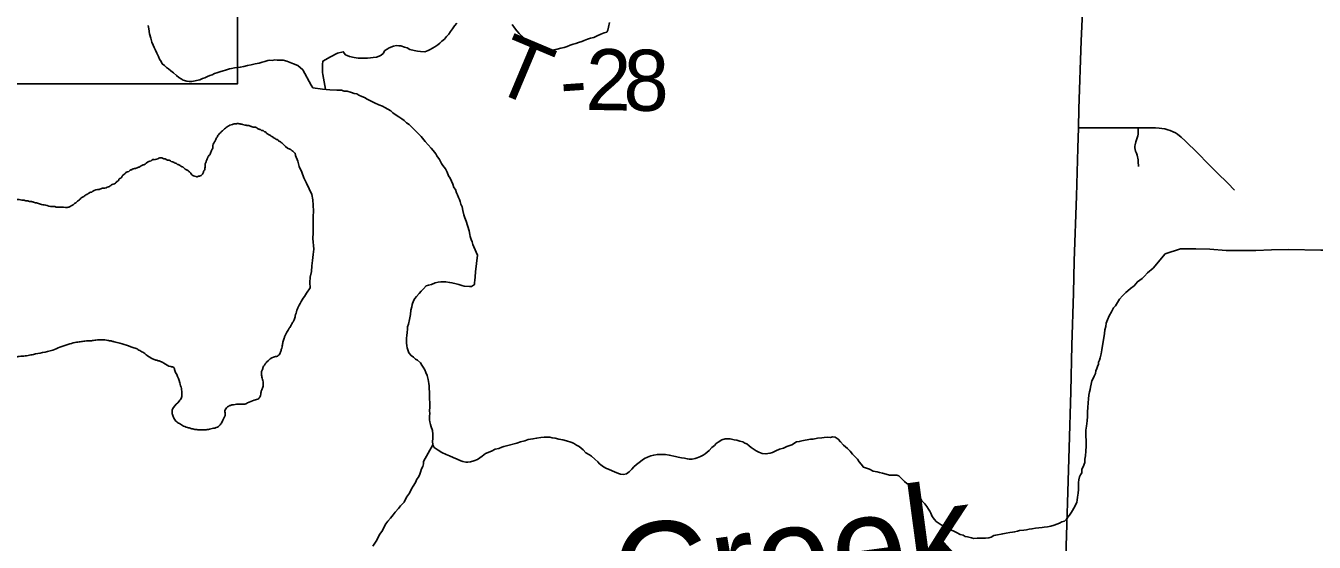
# Model space of a CAD drawing. Extents: x 0 to 34, y 0 to 22.
# Drawn here: x 26.822 to 28.021, y 15.894 to 16.375 of the extents above; entities that cross this region are included whole.
import ezdxf

# ---------------------------------------------------------------- set-up
doc = ezdxf.new("R2010")
doc.units = 0
for name, color, linetype in [('GM_X_City_Street', 7, 'Continuous'), ('GM_X_Minor_Lake', 7, 'Continuous'), ('GM_X_Minor_River', 7, 'Continuous'), ('GM_X_Minor_River_Text', 7, 'Continuous'), ('GM_X_State_Route', 7, 'Continuous'), ('GM_X_Township_Road_Text', 7, 'Continuous'), ('SH_Masking', 7, 'Continuous'), ('SH_Text', 7, 'Continuous')]:
    doc.layers.add(name, color=color, linetype=linetype)

msp = doc.modelspace()

# ---------------------------------------------------------------- linework, layer by layer
at = {"layer": 'GM_X_City_Street'}
for points in [[(27.8013, 16.2796), (27.8121, 16.2796), (27.8175, 16.2796), (27.8364, 16.2796), (27.857, 16.2797), (27.8646, 16.2797), (27.873, 16.2796), (27.8763, 16.2794), (27.8788, 16.2791), (27.8817, 16.2786), (27.8844, 16.2779), (27.8868, 16.2771), (27.8895, 16.276), (27.8916, 16.2749), (27.8934, 16.2737), (27.8969, 16.2711), (27.9007, 16.2675), (27.9123, 16.256), (27.9221, 16.2462), (27.9305, 16.2377), (27.9402, 16.2281), (27.9465, 16.2218)], [(27.8572, 16.2437), (27.857, 16.2485), (27.8569, 16.2498), (27.8567, 16.2516), (27.8564, 16.2528), (27.8559, 16.2543), (27.8552, 16.2561), (27.8544, 16.2579), (27.854, 16.2594), (27.8537, 16.261), (27.8537, 16.2626), (27.854, 16.264), (27.8547, 16.2665), (27.8561, 16.2705), (27.8566, 16.2723), (27.8568, 16.2738), (27.857, 16.2769), (27.857, 16.2797)]]:
    msp.add_lwpolyline(points, dxfattribs=at)
at = {"layer": 'GM_X_Minor_Lake'}
msp.add_lwpolyline([(27.0831, 16.126), (27.0863, 16.1308), (27.086, 16.1358), (27.0863, 16.1409), (27.0877, 16.1459), (27.088, 16.1513), (27.0887, 16.1563), (27.0893, 16.1617), (27.0897, 16.1667), (27.089, 16.1768), (27.0893, 16.1819), (27.0893, 16.1973), (27.0896, 16.2023), (27.0893, 16.2077), (27.089, 16.2127), (27.0879, 16.2178), (27.0856, 16.2228), (27.0829, 16.2282), (27.0806, 16.2332), (27.0785, 16.2383), (27.0762, 16.2436), (27.0748, 16.2487), (27.0728, 16.254), (27.0723, 16.256)], dxfattribs=at)
for points in [[(27.0723, 16.256), (27.0718, 16.2563), (27.0707, 16.2575), (27.0696, 16.2583), (27.0685, 16.2594), (27.0674, 16.2598), (27.0599, 16.2657), (27.0588, 16.2665), (27.0573, 16.2673), (27.0562, 16.2685), (27.0551, 16.2689), (27.0539, 16.2697), (27.0524, 16.2705), (27.0502, 16.272), (27.0487, 16.2728), (27.0476, 16.2736), (27.0461, 16.2744), (27.045, 16.2756), (27.0439, 16.276), (27.0427, 16.2771), (27.0412, 16.2772), (27.0401, 16.278), (27.039, 16.2784), (27.0379, 16.2788), (27.0367, 16.2796), (27.0345, 16.2804), (27.0333, 16.2804), (27.0318, 16.2808), (27.0307, 16.2812), (27.0292, 16.2817), (27.0281, 16.2817), (27.0269, 16.2821), (27.0258, 16.2821), (27.0235, 16.2829), (27.0224, 16.283), (27.0213, 16.2834), (27.0201, 16.2834), (27.019, 16.2838), (27.0179, 16.2835), (27.0156, 16.2835), (27.014, 16.2828), (27.0117, 16.2821), (27.0083, 16.2799), (27.0067, 16.2788), (27.004, 16.2762), (27.0028, 16.2751), (27.0017, 16.274), (27.0005, 16.2725), (26.9997, 16.271), (26.9989, 16.2699), (26.9981, 16.2676), (26.9973, 16.2665), (26.9957, 16.262), (26.9957, 16.2608), (26.9952, 16.2597), (26.9945, 16.2586), (26.9932, 16.2552), (26.9925, 16.2541), (26.9913, 16.2526), (26.9909, 16.2515), (26.9901, 16.25), (26.9897, 16.2488), (26.9892, 16.2473), (26.9888, 16.2462), (26.9888, 16.2439), (26.9884, 16.242), (26.9883, 16.2409), (26.9875, 16.2398), (26.9871, 16.2383), (26.9856, 16.236), (26.984, 16.2349), (26.9825, 16.2346), (26.9813, 16.2342), (26.9802, 16.2343), (26.9779, 16.2351), (26.9757, 16.2367), (26.9746, 16.2382), (26.9735, 16.239), (26.9724, 16.2402), (26.9712, 16.2406), (26.9701, 16.2413), (26.969, 16.2421)], [(26.969, 16.2421), (26.9679, 16.2433), (26.9668, 16.2437), (26.9653, 16.2445), (26.9641, 16.2453), (26.963, 16.2457), (26.9619, 16.2465), (26.9604, 16.2469), (26.9593, 16.2477), (26.957, 16.2485), (26.9559, 16.2493), (26.9548, 16.2497), (26.9536, 16.2497), (26.9525, 16.2501), (26.9514, 16.2509), (26.9502, 16.2509), (26.9491, 16.2514), (26.9457, 16.2514), (26.9411, 16.25), (26.94, 16.2501), (26.9384, 16.249), (26.9361, 16.2483), (26.9315, 16.2453), (26.9304, 16.245), (26.9292, 16.2442), (26.9273, 16.2432), (26.9261, 16.2428), (26.9246, 16.2421), (26.9212, 16.2414), (26.92, 16.2407), (26.9189, 16.2403), (26.9177, 16.2392), (26.9154, 16.2385), (26.9146, 16.2374), (26.9131, 16.2363), (26.9119, 16.2352), (26.9103, 16.2329), (26.9084, 16.2318), (26.908, 16.2307), (26.9064, 16.2296), (26.9053, 16.2281), (26.903, 16.2274), (26.9003, 16.2256), (26.8987, 16.2249), (26.8942, 16.2235), (26.893, 16.2235), (26.8915, 16.2228), (26.8899, 16.2224), (26.8842, 16.2207), (26.8831, 16.2199), (26.8815, 16.2196), (26.8804, 16.2189), (26.8788, 16.2178), (26.8777, 16.2174), (26.8765, 16.2163), (26.875, 16.2156), (26.8738, 16.2149), (26.8723, 16.2134), (26.8711, 16.2123), (26.8699, 16.2115), (26.8688, 16.2104), (26.8676, 16.2097), (26.8665, 16.2086), (26.8641, 16.2071), (26.8618, 16.206), (26.8603, 16.2057), (26.8535, 16.2059), (26.8501, 16.2059), (26.8489, 16.2064), (26.8448, 16.2065), (26.8387, 16.2081), (26.8376, 16.2081), (26.8353, 16.2086), (26.8335, 16.2094), (26.8297, 16.2102), (26.827, 16.2111), (26.8259, 16.2111), (26.8244, 16.2115), (26.821, 16.212), (26.8195, 16.2124), (26.818, 16.2124), (26.8157, 16.2129), (26.8138, 16.2129), (26.8127, 16.2133), (26.8104, 16.2137), (26.8093, 16.2138), (26.8078, 16.2142), (26.8051, 16.2146), (26.804, 16.2147), (26.8017, 16.2151), (26.8006, 16.2151), (26.7991, 16.2155), (26.7979, 16.2156), (26.7968, 16.216), (26.7949, 16.2164), (26.793, 16.2165), (26.7919, 16.2169)], [(26.7254, 16.1829), (26.725, 16.1705), (26.7242, 16.1679), (26.7222, 16.1638), (26.7206, 16.16), (26.719, 16.157), (26.7177, 16.1536), (26.7173, 16.1498), (26.7167, 16.1434), (26.7166, 16.1407), (26.7158, 16.137), (26.7156, 16.1305), (26.7159, 16.1275), (26.717, 16.1244), (26.7192, 16.1209), (26.7221, 16.1174), (26.728, 16.1112), (26.7314, 16.108), (26.7332, 16.1049), (26.7353, 16.0981), (26.7356, 16.095), (26.737, 16.0919), (26.7381, 16.0889), (26.7395, 16.0846), (26.7409, 16.0808), (26.7435, 16.0777), (26.7461, 16.0753), (26.7498, 16.073), (26.7528, 16.0714), (26.7559, 16.0701), (26.7592, 16.0689), (26.7634, 16.0673), (26.7675, 16.066), (26.7713, 16.0655), (26.774, 16.0651), (26.777, 16.065), (26.7812, 16.0645), (26.7869, 16.0644), (26.7926, 16.0646), (26.7987, 16.0652), (26.8025, 16.0655), (26.8067, 16.0661), (26.812, 16.0663), (26.8155, 16.067), (26.8185, 16.0673), (26.8239, 16.0679), (26.8288, 16.0689), (26.8373, 16.0706), (26.8468, 16.073), (26.8534, 16.0755), (26.861, 16.078), (26.8676, 16.0801), (26.8725, 16.0807), (26.8767, 16.0813), (26.8828, 16.0816), (26.887, 16.0822), (26.8901, 16.0825), (26.8954, 16.0824), (26.898, 16.0819), (26.9011, 16.0814), (26.9041, 16.0806), (26.9094, 16.0793), (26.9173, 16.0768), (26.9203, 16.0756), (26.9245, 16.0744), (26.9278, 16.0724), (26.9316, 16.0704), (26.9346, 16.068), (26.9398, 16.0648), (26.9428, 16.0636), (26.9458, 16.0628), (26.9503, 16.0607), (26.9567, 16.0575), (26.9594, 16.0567), (26.9604, 16.054), (26.9622, 16.0502), (26.9651, 16.0425), (26.9665, 16.0371), (26.9671, 16.0322), (26.9666, 16.0288), (26.9646, 16.0254), (26.9591, 16.0195), (26.9579, 16.0161), (26.9582, 16.013), (26.9596, 16.0096), (26.9622, 16.0061), (26.9656, 16.0041), (26.9697, 16.0017), (26.9723, 16.0009), (26.9754, 16), (26.9791, 15.9992), (26.9829, 15.9987), (26.9864, 15.9986), (26.9906, 15.9989), (26.9951, 15.9999), (27.0001, 16.0013), (27.0032, 16.0042)], [(27.0032, 16.0042), (27.0052, 16.0076), (27.0064, 16.0102), (27.0073, 16.0129), (27.007, 16.0163), (27.0094, 16.02), (27.0121, 16.0215), (27.0151, 16.0221), (27.0178, 16.0225), (27.022, 16.0227), (27.0246, 16.0226), (27.0281, 16.0237), (27.0343, 16.0262), (27.0385, 16.028), (27.0401, 16.0306), (27.0405, 16.0332), (27.0414, 16.0359), (27.0426, 16.0393), (27.0427, 16.0419), (27.0423, 16.0446), (27.0413, 16.0488), (27.041, 16.0522), (27.0419, 16.0549), (27.0431, 16.0579), (27.0462, 16.062), (27.0524, 16.0664), (27.0559, 16.0674), (27.0586, 16.0704), (27.0595, 16.0734), (27.0603, 16.076), (27.0608, 16.0795), (27.062, 16.0832), (27.0628, 16.0859), (27.064, 16.0885), (27.0664, 16.0926), (27.0684, 16.0956), (27.07, 16.0986), (27.0716, 16.1012), (27.0725, 16.1046), (27.0741, 16.1099), (27.0753, 16.1129), (27.0831, 16.126)]]:
    msp.add_spline(points, degree=3, dxfattribs=at)
at = {"layer": 'GM_X_Minor_River'}
for points in [[(26.9357, 16.375), (26.9364, 16.3719), (26.937, 16.367), (26.938, 16.3632), (26.9391, 16.3593), (26.9402, 16.3567), (26.9412, 16.3543), (26.9423, 16.352), (26.9438, 16.349), (26.9452, 16.3459), (26.9463, 16.3436), (26.9478, 16.3413), (26.9488, 16.3393), (26.9507, 16.3378), (26.9526, 16.3358), (26.9544, 16.3346), (26.9567, 16.3327), (26.9593, 16.3307), (26.9619, 16.3284), (26.9641, 16.3264), (26.9663, 16.3252), (26.9682, 16.324)], [(27.1006, 16.3155), (27.0983, 16.3292), (27.098, 16.3311), (27.0977, 16.3342), (27.0978, 16.3361), (27.0978, 16.3387), (27.0983, 16.3418), (27.1053, 16.3458), (27.1118, 16.349), (27.1172, 16.3504), (27.1194, 16.3476), (27.1231, 16.346), (27.1273, 16.3451), (27.1311, 16.3446), (27.1337, 16.3446), (27.1364, 16.3445), (27.1398, 16.3444), (27.1425, 16.3447), (27.1451, 16.345), (27.1482, 16.3453), (27.1505, 16.3464), (27.1524, 16.3474), (27.1544, 16.3489), (27.1559, 16.3515), (27.1579, 16.353), (27.1598, 16.3541), (27.164, 16.3555), (27.1667, 16.3562), (27.169, 16.3561), (27.1709, 16.356), (27.1743, 16.3548), (27.1765, 16.354), (27.1791, 16.3524), (27.1833, 16.3515), (27.1863, 16.351), (27.189, 16.3506), (27.1931, 16.3505), (27.1962, 16.3515), (27.1981, 16.3526), (27.2001, 16.3537), (27.2024, 16.3551), (27.2051, 16.357), (27.207, 16.3584), (27.209, 16.3603), (27.2113, 16.3621), (27.2133, 16.3647), (27.2153, 16.3669), (27.2169, 16.3692), (27.2188, 16.3718), (27.2208, 16.3744), (27.2228, 16.377)], [(27.2744, 16.3759), (27.2766, 16.3728), (27.2788, 16.37), (27.281, 16.3673), (27.2832, 16.365), (27.285, 16.363), (27.288, 16.3588), (27.2902, 16.3564), (27.292, 16.3552), (27.2943, 16.3536), (27.2973, 16.3528), (27.3007, 16.3519), (27.3026, 16.3515), (27.3064, 16.3518), (27.3098, 16.352), (27.3132, 16.3523), (27.3163, 16.353), (27.3197, 16.3537), (27.3228, 16.3543), (27.3255, 16.3554), (27.3282, 16.3565), (27.3312, 16.3575), (27.3335, 16.3582), (27.3362, 16.3589), (27.3393, 16.3599), (27.3412, 16.361), (27.3443, 16.3621)], [(27.3443, 16.3621), (27.3473, 16.3631), (27.3504, 16.3638), (27.3535, 16.3652), (27.3569, 16.3667), (27.36, 16.3681), (27.3623, 16.3688), (27.3635, 16.3706), (27.364, 16.3733), (27.3648, 16.3775)], [(26.9682, 16.324), (26.9716, 16.3232), (26.9739, 16.3228), (26.9762, 16.3227), (26.9838, 16.3244), (26.9861, 16.3255), (26.9884, 16.3262), (26.9907, 16.3273), (26.993, 16.3283), (26.9953, 16.329), (26.9972, 16.3301), (26.9995, 16.3308), (27.0022, 16.3319), (27.0053, 16.3326), (27.0076, 16.3333), (27.0095, 16.334), (27.0114, 16.3347), (27.0133, 16.335), (27.016, 16.3354), (27.0183, 16.3357), (27.0213, 16.336), (27.0248, 16.3367), (27.0282, 16.3377), (27.0316, 16.3384), (27.0351, 16.3391), (27.0389, 16.3397), (27.0416, 16.3408), (27.0442, 16.3415), (27.0469, 16.3422), (27.0488, 16.3425), (27.0511, 16.3424), (27.0534, 16.3428), (27.0557, 16.3427), (27.0591, 16.3426), (27.0614, 16.3426), (27.0648, 16.3417), (27.0678, 16.3405), (27.0708, 16.3393), (27.0749, 16.3377)], [(27.0794, 16.3337), (27.0749, 16.3377)], [(27.0794, 16.3337), (27.0874, 16.3193), (27.0889, 16.3169), (27.0979, 16.3155), (27.1048, 16.315), (27.1112, 16.3148), (27.1154, 16.3147), (27.118, 16.3138), (27.1207, 16.3138), (27.1248, 16.3125), (27.1274, 16.3117), (27.1297, 16.3112), (27.1316, 16.31), (27.1346, 16.3088), (27.1368, 16.308), (27.1394, 16.3064), (27.1424, 16.3048), (27.1462, 16.3028), (27.1503, 16.3011), (27.1537, 16.2999), (27.1559, 16.2987), (27.1615, 16.2955), (27.1634, 16.2935), (27.1664, 16.2915), (27.169, 16.2899), (27.1716, 16.288), (27.1738, 16.2864), (27.176, 16.2844), (27.1786, 16.2828), (27.1805, 16.2809), (27.1827, 16.2785), (27.1849, 16.2762), (27.1875, 16.2738), (27.1897, 16.2715), (27.1934, 16.2668), (27.1963, 16.2637), (27.1989, 16.2609), (27.2007, 16.2586), (27.2033, 16.2555), (27.2044, 16.2536), (27.2066, 16.2501), (27.2087, 16.2466), (27.2098, 16.2447), (27.2124, 16.2415), (27.2138, 16.2385), (27.2152, 16.235), (27.2167, 16.2327), (27.2178, 16.23), (27.2192, 16.2273), (27.2202, 16.2242), (27.2217, 16.2223), (27.2224, 16.2192), (27.2235, 16.2173), (27.2245, 16.215), (27.2252, 16.213), (27.2259, 16.2111), (27.2266, 16.2088), (27.2277, 16.2061), (27.2284, 16.2027), (27.2294, 16.1988), (27.2304, 16.1961), (27.2315, 16.1927), (27.2343, 16.1839), (27.2349, 16.1804), (27.2353, 16.1785), (27.2363, 16.1758), (27.237, 16.1735), (27.2377, 16.1712), (27.2388, 16.1689), (27.2421, 16.1613)], [(27.8709, 16.149), (27.8821, 16.1625), (27.8963, 16.1671), (27.9104, 16.1671), (27.9237, 16.1668), (27.9389, 16.1656), (27.953, 16.1657), (27.9663, 16.1657), (27.9811, 16.1661), (27.9967, 16.1665), (28.0268, 16.1658), (28.0401, 16.1658), (28.0557, 16.1654), (28.0705, 16.1643), (28.0853, 16.1632), (28.1157, 16.1609), (28.1289, 16.1602), (28.1426, 16.1595), (28.1575, 16.1595), (28.1711, 16.1595), (28.1856, 16.1599), (28.1997, 16.1607)], [(27.2421, 16.1613), (27.2403, 16.1456), (27.2398, 16.1411), (27.2397, 16.1376), (27.2393, 16.1358), (27.2392, 16.1339), (27.2365, 16.132), (27.2346, 16.132), (27.2297, 16.1325), (27.2274, 16.133), (27.2248, 16.1338), (27.2221, 16.1346), (27.2183, 16.1355), (27.2161, 16.1359), (27.2126, 16.1363), (27.2104, 16.1364), (27.2081, 16.1364), (27.2054, 16.1361), (27.2027, 16.1354), (27.1993, 16.134), (27.1966, 16.1333), (27.1943, 16.1326), (27.1919, 16.13), (27.1896, 16.1277), (27.1877, 16.1255), (27.1853, 16.1229), (27.1838, 16.121), (27.1826, 16.1187), (27.1813, 16.1153), (27.1809, 16.1131), (27.1801, 16.11), (27.1796, 16.1059), (27.1788, 16.1013), (27.1779, 16.0971), (27.1771, 16.0945), (27.177, 16.0922), (27.1766, 16.0896), (27.1762, 16.0861), (27.1761, 16.0842), (27.176, 16.0797), (27.1763, 16.077), (27.1767, 16.0751), (27.1774, 16.0732), (27.1781, 16.0705), (27.1803, 16.0678), (27.1826, 16.0662), (27.1845, 16.0646), (27.1863, 16.0635), (27.1889, 16.0611), (27.1904, 16.0588), (27.1915, 16.0569), (27.193, 16.0545), (27.1941, 16.0522), (27.1952, 16.0492), (27.1962, 16.0457), (27.1966, 16.0438), (27.1969, 16.0419), (27.1972, 16.0396), (27.1972, 16.0377), (27.1975, 16.0331), (27.1974, 16.0286), (27.1977, 16.0228), (27.1976, 16.0194), (27.1975, 16.0168), (27.1978, 16.0137), (27.1974, 16.0118), (27.1974, 16.0099), (27.1973, 16.008), (27.1977, 16.0061), (27.1984, 16.0038), (27.1991, 16.0015), (27.2002, 15.998), (27.2005, 15.9946), (27.2004, 15.9927), (27.2004, 15.9904), (27.2003, 15.9881), (27.2006, 15.9847), (27.2017, 15.9824), (27.2055, 15.9797), (27.2089, 15.9777), (27.213, 15.9757), (27.216, 15.9745), (27.2194, 15.9729), (27.2232, 15.9713), (27.2266, 15.97), (27.2285, 15.9692), (27.2312, 15.9688), (27.2331, 15.9688), (27.2357, 15.9691), (27.2388, 15.9698), (27.2422, 15.9712), (27.2442, 15.9727), (27.2465, 15.9742), (27.2496, 15.9768), (27.255, 15.9789), (27.2584, 15.9808), (27.2619, 15.9814), (27.2646, 15.9825)], [(27.8016, 15.9523), (27.8024, 15.955), (27.8032, 15.9569), (27.8044, 15.9588), (27.8045, 15.9622), (27.8057, 15.9644), (27.8073, 15.9682), (27.8074, 15.9713), (27.8078, 15.9747), (27.8083, 15.9789), (27.8084, 15.9834), (27.8085, 15.9884), (27.8082, 15.9933), (27.8083, 15.9983), (27.8088, 16.0021), (27.8093, 16.007), (27.8097, 16.0112), (27.8098, 16.0154), (27.8099, 16.0195), (27.8104, 16.0237), (27.8108, 16.0275), (27.8109, 16.0309), (27.8117, 16.034), (27.8122, 16.0363), (27.8126, 16.0385), (27.813, 16.0412), (27.8139, 16.0442), (27.8151, 16.0465), (27.8159, 16.0487), (27.8171, 16.051), (27.8175, 16.0536), (27.8183, 16.0559), (27.8191, 16.0578), (27.8199, 16.0597), (27.82, 16.0616), (27.8208, 16.0635), (27.8216, 16.0657), (27.8224, 16.0695), (27.8232, 16.0733), (27.8255, 16.0885), (27.8259, 16.0919), (27.8268, 16.0949), (27.8272, 16.098), (27.8284, 16.101), (27.83, 16.1048), (27.832, 16.1085), (27.834, 16.1123), (27.8359, 16.1141), (27.8375, 16.1172), (27.8395, 16.1202), (27.8422, 16.1235), (27.8453, 16.1265), (27.8473, 16.128), (27.8496, 16.1302), (27.8531, 16.1328), (27.8562, 16.1365), (27.8585, 16.138), (27.8605, 16.1395), (27.8628, 16.1417), (27.8655, 16.1447), (27.8709, 16.149)], [(27.2006, 15.9847), (27.1919, 15.9693), (27.1919, 15.967), (27.1911, 15.9647), (27.1899, 15.9625), (27.1891, 15.9595), (27.1883, 15.9576), (27.1871, 15.9546), (27.1855, 15.9527), (27.1843, 15.9497), (27.1823, 15.9463), (27.1807, 15.9437), (27.1787, 15.9399), (27.176, 15.9361), (27.174, 15.9316), (27.1705, 15.9279), (27.1685, 15.9256), (27.1654, 15.9223), (27.1635, 15.9197), (27.1611, 15.9167), (27.1588, 15.9137), (27.1568, 15.9114), (27.1552, 15.9084), (27.1536, 15.905), (27.1513, 15.9017), (27.1477, 15.8953), (27.1446, 15.8904)], [(27.2646, 15.9825), (27.2665, 15.9832), (27.2692, 15.984), (27.2787, 15.9864), (27.2822, 15.9875), (27.286, 15.9885), (27.2891, 15.9896), (27.2937, 15.9903), (27.2971, 15.9909), (27.3009, 15.9916), (27.304, 15.9919), (27.307, 15.9919), (27.3093, 15.9918), (27.3116, 15.9914), (27.3143, 15.9909), (27.3177, 15.9901), (27.3215, 15.9893), (27.3249, 15.9884), (27.329, 15.9872), (27.3313, 15.9864), (27.3343, 15.9844), (27.3366, 15.9832), (27.3403, 15.9801), (27.3429, 15.9774), (27.3463, 15.9754), (27.3482, 15.9742), (27.3512, 15.9715), (27.3542, 15.9691), (27.3556, 15.9672), (27.3594, 15.9644), (27.362, 15.9629), (27.3639, 15.9621), (27.3673, 15.9605), (27.3696, 15.9596), (27.3733, 15.958), (27.3752, 15.9576), (27.3779, 15.9572), (27.3806, 15.9579), (27.3833, 15.9597), (27.3856, 15.9623), (27.3876, 15.9642), (27.3899, 15.9664), (27.3926, 15.9683), (27.3953, 15.9705), (27.3976, 15.972), (27.4003, 15.9734), (27.4034, 15.9745), (27.4061, 15.9752), (27.4095, 15.9759), (27.4114, 15.9758), (27.4137, 15.9758), (27.4171, 15.9757), (27.4206, 15.9753), (27.4262, 15.974), (27.4289, 15.9732), (27.4319, 15.9727), (27.4346, 15.9723), (27.4372, 15.9718), (27.4391, 15.9714), (27.4418, 15.9714), (27.4445, 15.9721), (27.4464, 15.9728), (27.4495, 15.9739), (27.4522, 15.9753), (27.4541, 15.9764), (27.4576, 15.9794), (27.4603, 15.9824), (27.4626, 15.9842), (27.4642, 15.9861), (27.4661, 15.9872), (27.4696, 15.9894), (27.4727, 15.9905), (27.4772, 15.9904), (27.481, 15.9895), (27.4833, 15.9891), (27.4863, 15.9883), (27.489, 15.9875), (27.4909, 15.9863), (27.4927, 15.9858), (27.495, 15.9839), (27.4969, 15.9823), (27.4987, 15.9811), (27.5014, 15.9792), (27.504, 15.978), (27.507, 15.9768), (27.5104, 15.9763), (27.5124, 15.9767), (27.5143, 15.977), (27.5166, 15.9777), (27.5196, 15.9792), (27.5231, 15.9806), (27.5269, 15.9817), (27.53, 15.9831), (27.5327, 15.9842), (27.5346, 15.9849), (27.5389, 15.9875), (27.5415, 15.9878), (27.5438, 15.9885), (27.5519, 15.9899), (27.5545, 15.9902), (27.5584, 15.9909)], [(27.5584, 15.9909), (27.5625, 15.9912), (27.5648, 15.9915), (27.5679, 15.9918), (27.5706, 15.9917), (27.5725, 15.9921), (27.5748, 15.992), (27.5778, 15.9901), (27.58, 15.9877), (27.5826, 15.9846), (27.5863, 15.9815), (27.5889, 15.9788), (27.5912, 15.976), (27.593, 15.9741), (27.5956, 15.9714), (27.5971, 15.9691), (27.599, 15.9667), (27.6012, 15.964), (27.6042, 15.9632), (27.6069, 15.962), (27.6103, 15.9604), (27.614, 15.9596), (27.6163, 15.9591), (27.619, 15.9583), (27.6224, 15.9575), (27.6254, 15.9566), (27.6292, 15.9566), (27.6323, 15.9565), (27.6342, 15.9561), (27.6371, 15.9533), (27.6394, 15.9506), (27.6416, 15.9487), (27.6443, 15.9475), (27.6457, 15.9455), (27.6483, 15.9428), (27.6513, 15.9397), (27.6535, 15.9366), (27.6557, 15.9327), (27.6583, 15.93), (27.6602, 15.9273), (27.6617, 15.925), (27.6631, 15.9231), (27.6639, 15.9211), (27.6653, 15.9181), (27.6672, 15.9154), (27.669, 15.9134), (27.6709, 15.9122), (27.6735, 15.9103), (27.6754, 15.9095), (27.6807, 15.9063), (27.6848, 15.9047), (27.6879, 15.9031), (27.6913, 15.9015), (27.6939, 15.9007), (27.6958, 15.8995), (27.6981, 15.8991), (27.7018, 15.8982), (27.7041, 15.8978), (27.7072, 15.8981), (27.7106, 15.898), (27.7125, 15.898), (27.7148, 15.8979), (27.7178, 15.8982), (27.7201, 15.899), (27.7225, 15.9004), (27.7244, 15.9008), (27.7309, 15.9021), (27.7339, 15.9025), (27.7374, 15.9031), (27.74, 15.9035), (27.7419, 15.9038), (27.7446, 15.9045), (27.7465, 15.9052), (27.7504, 15.9055), (27.753, 15.9058), (27.7553, 15.9062), (27.758, 15.9065), (27.7614, 15.9072), (27.7645, 15.9075), (27.7675, 15.9078), (27.7695, 15.9081), (27.7725, 15.9085), (27.7756, 15.9091), (27.7786, 15.9102), (27.7813, 15.9109), (27.7836, 15.912), (27.7859, 15.9131), (27.7882, 15.9138), (27.7902, 15.9157), (27.7914, 15.9176), (27.7929, 15.9194), (27.7949, 15.922), (27.798, 15.9273), (27.7997, 15.9315), (27.8001, 15.9333), (27.8005, 15.936), (27.801, 15.9398), (27.8014, 15.9432), (27.8015, 15.9474), (27.8012, 15.9497), (27.8016, 15.9523)]]:
    msp.add_lwpolyline(points, dxfattribs=at)
at = {"layer": 'GM_X_State_Route'}
msp.add_lwpolyline([(27.7865, 15.7302), (27.787, 15.7819), (27.7876, 15.8117), (27.7887, 15.8521), (27.7901, 15.9005), (27.7917, 15.9514), (27.7926, 15.9819), (27.7941, 16.034), (27.7953, 16.0775), (27.7966, 16.126), (27.7974, 16.1558), (27.7994, 16.216), (27.8007, 16.2607), (27.8013, 16.2796), (27.8018, 16.2974), (27.8037, 16.3607), (27.805, 16.3876)], dxfattribs=at)
at = {"layer": 'SH_Masking'}
msp.add_lwpolyline([(25.2742, 16.8205), (27.0187, 16.8205), (27.0187, 16.3205), (25.2742, 16.3205)], close=True, dxfattribs=at)
at = {"layer": 'SH_Text'}
msp.add_lwpolyline([(25.2742, 16.3205), (27.0187, 16.3205), (27.0187, 16.8205), (25.2742, 16.8205)], close=True, dxfattribs=at)

# ---------------------------------------------------------------- texts
at = {"layer": 'GM_X_Minor_River_Text'}
msp.add_text('Creek', height=0.09474, rotation=7.6238, dxfattribs=at).set_placement((27.3747, 15.8126))
at = {"layer": 'GM_X_Township_Road_Text'}
for s, rotation, p in [('T', 337.1711, (27.2529, 16.316)), ('2', 359.0164, (27.3424, 16.2964)), ('8', 359.1946, (27.3776, 16.2958)), ('-', 3.984, (27.3204, 16.2948))]:
    msp.add_text(s, height=0.0568, rotation=rotation, dxfattribs=at).set_placement(p)

doc.saveas('drawing.dxf')
